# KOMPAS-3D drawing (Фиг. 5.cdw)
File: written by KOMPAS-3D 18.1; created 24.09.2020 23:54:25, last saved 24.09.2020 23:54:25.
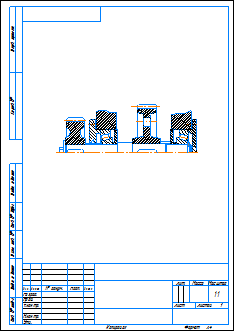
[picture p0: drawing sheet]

Sheet 1: A4, portrait

Document properties: Автор: user; Полное имя файла: C:\Users\user\Desktop\Задания\Фиг. 5.cdw

Title block, sheet 1: scale: 1:1; Количество листов документа: 1; Форматы листов документа: A4

Dimensions and other numbers on the sheet: 1:1; 1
